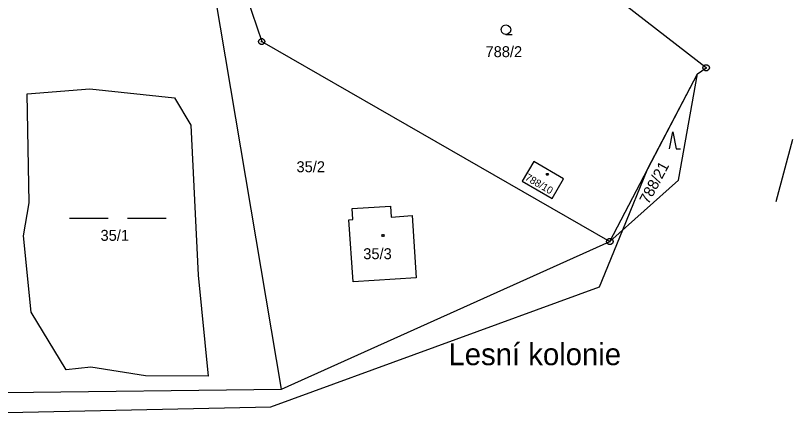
# Model space of a CAD drawing. Extents: x -759060 to -757386, y -1172273 to -1170948.
# Drawn here: x -757696.5 to -757575.9, y -1171349 to -1171287.4 of the extents above; entities that cross this region are included whole.
import ezdxf

# ---------------------------------------------------------------- set-up
doc = ezdxf.new("R2010")
doc.units = 0
for name, color, linetype in [('Vrstva 1', 7, 'Continuous'), ('Vrstva 11', 7, 'Continuous'), ('Vrstva 12', 7, 'Continuous'), ('Vrstva 2', 7, 'Continuous'), ('Vrstva 3', 7, 'Continuous'), ('Vrstva 5', 7, 'Continuous'), ('Vrstva 7', 7, 'Continuous'), ('Vrstva 8', 7, 'Continuous')]:
    doc.layers.add(name, color=color, linetype=linetype)

msp = doc.modelspace()

# ---------------------------------------------------------------- linework, layer by layer
at = {"layer": 'Vrstva 1'}
for p, q in [((-757655.25, -1171345.35), (-757667.12, -1171274.77)), ((-757662.93, -1171277.85), (-757658.33, -1171291.42)), ((-757589.34, -1171295.49), (-757601.7, -1171285.92)), ((-757658.33, -1171291.42), (-757604.28, -1171322.45)), ((-757590.7, -1171296.4), (-757589.34, -1171295.49)), ((-757604.28, -1171322.45), (-757590.7, -1171296.4)), ((-757593.65, -1171312.93), (-757590.7, -1171296.4)), ((-757578.49, -1171316.23), (-757575.86, -1171306.56)), ((-757616.09, -1171310.02), (-757617.88, -1171313.09)), ((-757611.47, -1171312.74), (-757616.09, -1171310.02)), ((-757617.88, -1171313.09), (-757613.25, -1171315.78)), ((-757613.25, -1171315.78), (-757611.47, -1171312.74)), ((-757604.28, -1171322.45), (-757593.65, -1171312.93)), ((-757578.49, -1171316.23), (-757578.49, -1171316.23)), ((-757644.28, -1171317.33), (-757638.34, -1171316.95)), ((-757644.17, -1171319.03), (-757644.28, -1171317.33)), ((-757638.34, -1171316.95), (-757638.22, -1171318.65)), ((-757644.79, -1171319.06), (-757644.17, -1171319.03)), ((-757644.13, -1171328.72), (-757644.79, -1171319.06)), ((-757638.22, -1171318.65), (-757634.96, -1171318.41)), ((-757634.96, -1171318.41), (-757634.35, -1171328.06)), ((-757655.25, -1171345.35), (-757604.28, -1171322.45)), ((-757634.35, -1171328.06), (-757644.13, -1171328.72)), ((-757698.05, -1171345.87), (-757655.25, -1171345.35))]:
    msp.add_line(p, q, dxfattribs=at)
at = {"layer": 'Vrstva 11'}
for p, q in [((-757589.34, -1171295.49), (-757601.7, -1171285.92)), ((-757590.7, -1171296.4), (-757589.34, -1171295.49)), ((-757598.37, -1171311.12), (-757590.7, -1171296.4)), ((-757694.75, -1171299.52), (-757684.99, -1171298.76)), ((-757694.44, -1171316.46), (-757694.75, -1171299.52)), ((-757684.99, -1171298.76), (-757671.85, -1171300.13)), ((-757671.85, -1171300.13), (-757669.33, -1171304.39)), ((-757669.33, -1171304.39), (-757668.21, -1171327.69)), ((-757602.27, -1171320.65), (-757598.37, -1171311.12)), ((-757695.32, -1171321.54), (-757694.44, -1171316.46)), ((-757694.12, -1171333.41), (-757695.32, -1171321.54)), ((-757605.87, -1171329.47), (-757602.27, -1171320.65)), ((-757668.21, -1171327.69), (-757666.62, -1171343.37)), ((-757656.89, -1171348.11), (-757605.87, -1171329.47)), ((-757688.67, -1171342.35), (-757694.12, -1171333.41)), ((-757684.85, -1171341.95), (-757688.67, -1171342.35)), ((-757676.37, -1171343.29), (-757684.85, -1171341.95)), ((-757666.62, -1171343.37), (-757676.37, -1171343.29)), ((-757697.79, -1171348.98), (-757656.89, -1171348.11))]:
    msp.add_line(p, q, dxfattribs=at)
at = {"layer": 'Vrstva 12'}
for p, q in [((-757616.09, -1171310.02), (-757617.88, -1171313.09)), ((-757611.47, -1171312.74), (-757616.09, -1171310.02)), ((-757617.88, -1171313.09), (-757613.25, -1171315.78)), ((-757613.25, -1171315.78), (-757611.47, -1171312.74)), ((-757644.28, -1171317.33), (-757638.34, -1171316.95)), ((-757644.17, -1171319.03), (-757644.28, -1171317.33)), ((-757638.34, -1171316.95), (-757638.22, -1171318.65)), ((-757644.79, -1171319.06), (-757644.17, -1171319.03)), ((-757644.13, -1171328.72), (-757644.79, -1171319.06)), ((-757638.22, -1171318.65), (-757634.96, -1171318.41)), ((-757634.96, -1171318.41), (-757634.35, -1171328.06)), ((-757634.35, -1171328.06), (-757644.13, -1171328.72))]:
    msp.add_line(p, q, dxfattribs=at)
at = {"layer": 'Vrstva 3'}
for p, q in [((-757688.18, -1171318.82), (-757682.18, -1171318.82)), ((-757679.18, -1171318.82), (-757673.18, -1171318.82))]:
    msp.add_line(p, q, dxfattribs=at)
for points in [[(-757620.41, -1171290.3), (-757620.79, -1171290.2), (-757621.06, -1171289.93), (-757621.16, -1171289.56), (-757621.06, -1171289.19), (-757620.79, -1171288.92), (-757620.42, -1171288.82), (-757620.05, -1171288.92), (-757619.78, -1171289.19), (-757619.68, -1171289.57), (-757619.78, -1171289.95), (-757620.05, -1171290.22), (-757620.43, -1171290.32), (-757619.43, -1171290.32)], [(-757595.012, -1171308.08), (-757594.51, -1171305.4), (-757594.008, -1171308.08), (-757593.338, -1171308.08)]]:
    msp.add_lwpolyline(points, dxfattribs=at)
at = {"layer": 'Vrstva 5'}
for points in [[(-757613.9, -1171311.87), (-757613.81, -1171312.02), (-757613.9, -1171312.17), (-757614.08, -1171312.17), (-757614.17, -1171312.02), (-757614.08, -1171311.87)], [(-757639.42, -1171321.37), (-757639.33, -1171321.52), (-757639.42, -1171321.67), (-757639.6, -1171321.67), (-757639.69, -1171321.52), (-757639.6, -1171321.37)]]:
    msp.add_lwpolyline(points, close=True, dxfattribs=at)
at = {"layer": 'Vrstva 8'}
for p, q in [((-757658.45, -1171291.42), (-757658.21, -1171291.42)), ((-757589.46, -1171295.49), (-757589.22, -1171295.49)), ((-757604.4, -1171322.45), (-757604.16, -1171322.45))]:
    msp.add_line(p, q, dxfattribs=at)
for points in [[(-757658.18, -1171290.94), (-757657.93, -1171291.12), (-757657.83, -1171291.41), (-757657.93, -1171291.7), (-757658.18, -1171291.88), (-757658.49, -1171291.88), (-757658.74, -1171291.7), (-757658.84, -1171291.41), (-757658.74, -1171291.12), (-757658.49, -1171290.94)], [(-757589.19, -1171295.01), (-757588.94, -1171295.19), (-757588.84, -1171295.48), (-757588.94, -1171295.77), (-757589.19, -1171295.95), (-757589.5, -1171295.95), (-757589.75, -1171295.77), (-757589.85, -1171295.48), (-757589.75, -1171295.19), (-757589.5, -1171295.01)], [(-757604.13, -1171321.97), (-757603.88, -1171322.15), (-757603.78, -1171322.44), (-757603.88, -1171322.73), (-757604.13, -1171322.91), (-757604.44, -1171322.91), (-757604.69, -1171322.73), (-757604.79, -1171322.44), (-757604.69, -1171322.15), (-757604.44, -1171321.97)]]:
    msp.add_lwpolyline(points, close=True, dxfattribs=at)

# ---------------------------------------------------------------- texts
at = {"layer": 'Vrstva 2'}
for s, p in [('788/2', (-757623.59, -1171293.83)), ('35/2', (-757652.931, -1171311.69)), ('35/1', (-757683.35, -1171322.34)), ('35/3', (-757642.565, -1171325.19))]:
    msp.add_text(s, height=1.7, dxfattribs=at).set_placement(p)
for s, height, rotation, p in [('788/21', 1.7, 61.93674, (-757598.297, -1171316.767)), ('788/10', 1.14, 329.79451, (-757617.561, -1171312.813))]:
    msp.add_text(s, height=height, rotation=rotation, dxfattribs=at).set_placement(p)
at = {"layer": 'Vrstva 7'}
msp.add_text('Lesní kolonie', height=3.4, dxfattribs=at).set_placement((-757629.336, -1171341.64))

doc.saveas('drawing.dxf')
